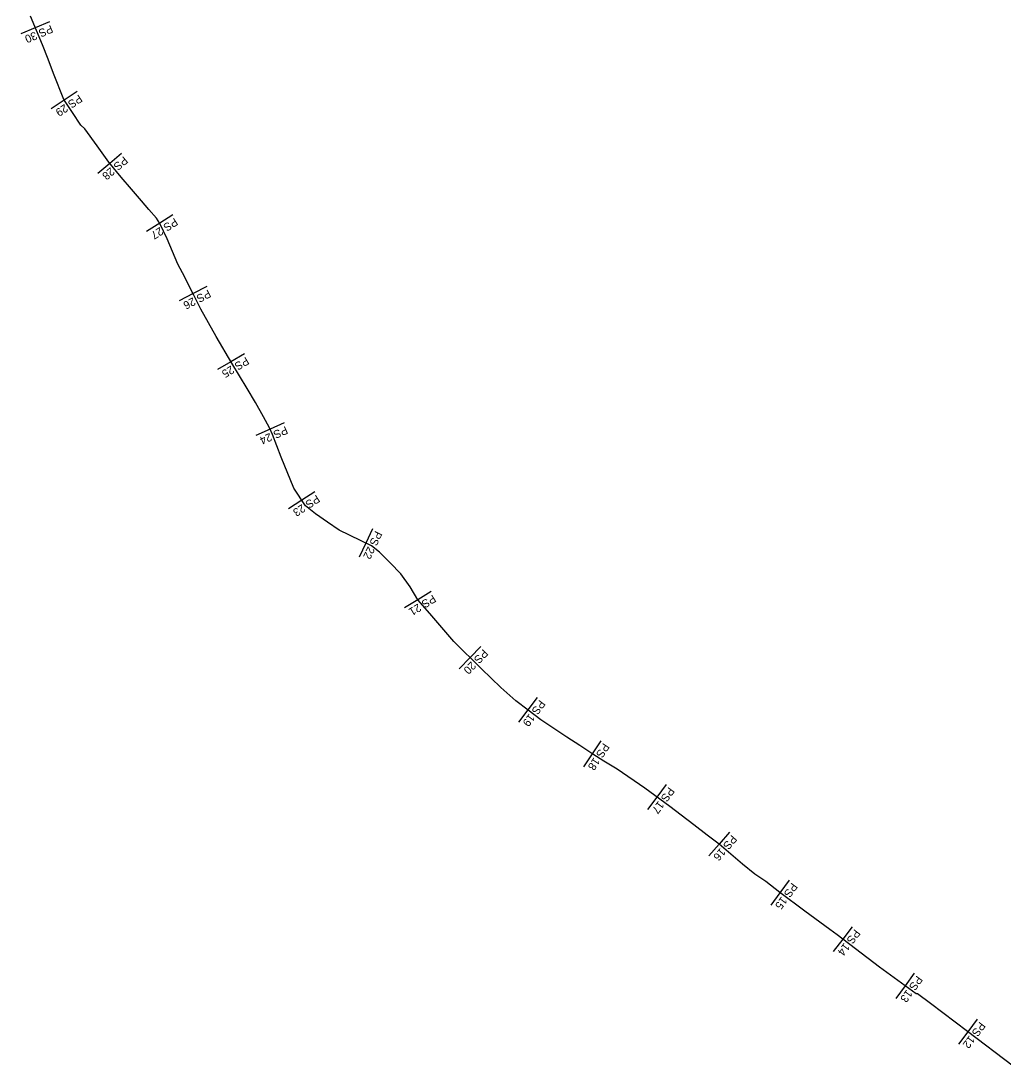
# Model space of a CAD drawing. Extents: x -844670 to -843025, y -997533 to -995513.
# Drawn here: x -844321 to -843691, y -997184 to -996514 of the extents above; entities that cross this region are included whole.
import ezdxf

# ---------------------------------------------------------------- set-up
doc = ezdxf.new("R2010")
doc.units = 0
doc.layers.add('Osa', color=7, linetype='Continuous')
doc.layers.add('Řezy', color=7, linetype='Continuous')

msp = doc.modelspace()

# ---------------------------------------------------------------- linework, layer by layer
at = {"layer": 'Osa'}
msp.add_lwpolyline([(-843685.02, -997184.17), (-843714.34, -997161.92), (-843737.99, -997144.05), (-843746.29, -997137.86), (-843747.28, -997137.77), (-843770.7, -997120.79), (-843797.77, -997100.1), (-843802.48, -997096.6), (-843818.53, -997084.86), (-843834.64, -997072.98), (-843843.67, -997065.86), (-843850.66, -997061.13), (-843858.57, -997054.8), (-843873.56, -997041.84), (-843881.27, -997036.04), (-843889.86, -997029.57), (-843897.98, -997023.38), (-843905.21, -997017.86), (-843921.14, -997005.98), (-843938.96, -996993.88), (-843947.49, -996988.62), (-843954.56, -996984.21), (-843962.93, -996978.74), (-843971.3, -996973.27), (-843979.6, -996967.7), (-843987.91, -996962.14), (-843995.94, -996956.08), (-844003.97, -996950.02), (-844013.59, -996941.43), (-844025.89, -996929.51), (-844043.74, -996912.06), (-844059.14, -996894.1), (-844066.71, -996885.26), (-844071.81, -996876.85), (-844077.67, -996868.54), (-844084.49, -996861.61), (-844091.32, -996854.69), (-844096.43, -996850.63), (-844117.33, -996840.69), (-844124.83, -996835.47), (-844132.33, -996830.24), (-844138.88, -996825.09), (-844146.3, -996813.66), (-844154.54, -996793.89), (-844157.3, -996786.63), (-844160.06, -996779.38), (-844161.95, -996775.05), (-844165.76, -996767.93), (-844170.99, -996758.84), (-844176.21, -996749.76), (-844186.05, -996733.62), (-844196.21, -996716.4), (-844205.92, -996698.84), (-844210.47, -996689.97), (-844217.82, -996675.58), (-844220.61, -996670.05), (-844224.05, -996661.97), (-844227.49, -996653.89), (-844232.17, -996644.05), (-844234.41, -996640.51), (-844239.23, -996635.04), (-844244.06, -996629.58), (-844250.52, -996621.94), (-844256.98, -996614.3), (-844264.96, -996604.81), (-844272.51, -996594.14), (-844280.44, -996583.43), (-844282.85, -996581.06), (-844288.34, -996572.81), (-844293.83, -996564.57), (-844300.43, -996547.97), (-844303.97, -996538.71), (-844307.53, -996529.45), (-844315.28, -996511.19)], dxfattribs=at)
at = {"layer": 'Řezy'}
for points in [[(-844302.95, -996514.65), (-844312.15, -996518.56), (-844321.36, -996522.47)], [(-844285.25, -996559.42), (-844293.57, -996564.96), (-844301.89, -996570.5)], [(-844256.73, -996599.05), (-844264.39, -996605.48), (-844272.05, -996611.91)], [(-844223.88, -996638.45), (-844232.33, -996643.8), (-844240.78, -996649.14)], [(-844202.07, -996684.43), (-844210.98, -996688.98), (-844219.88, -996693.53)], [(-844178.01, -996727.56), (-844186.63, -996732.64), (-844195.24, -996737.72)], [(-844152.41, -996771.89), (-844161.58, -996775.89), (-844170.74, -996779.9)], [(-844132.87, -996815.98), (-844141.26, -996821.42), (-844149.65, -996826.86)], [(-844095.87, -996839.82), (-844100.16, -996848.85), (-844104.45, -996857.89)], [(-844058.22, -996879.98), (-844066.77, -996885.17), (-844075.32, -996890.35)], [(-844026.31, -996915.11), (-844033.3, -996922.26), (-844040.29, -996929.41)], [(-843990.28, -996947.82), (-843996.3, -996955.8), (-844002.32, -996963.79)], [(-843949.51, -996975.57), (-843954.99, -996983.94), (-843960.46, -996992.3)], [(-843907.47, -997003.7), (-843913.44, -997011.72), (-843919.42, -997019.74)], [(-843867.01, -997034.29), (-843873.55, -997041.85), (-843880.08, -997049.42)], [(-843828.6, -997065.01), (-843834.53, -997073.06), (-843840.47, -997081.11)], [(-843788.23, -997094.8), (-843794.3, -997102.75), (-843800.37, -997110.69)], [(-843748.4, -997124.6), (-843754.27, -997132.7), (-843760.14, -997140.79)], [(-843707.99, -997154.18), (-843714.04, -997162.15), (-843720.08, -997170.11)]]:
    msp.add_lwpolyline(points, dxfattribs=at)

# ---------------------------------------------------------------- texts
for s, rotation, p in [('PS 30', 203.01087, (-844302.14, -996516.54)), ('PS 29', 213.666, (-844284.11, -996561.12)), ('PS 28', 220.00973, (-844255.41, -996600.62)), ('PS 27', 212.32433, (-844222.78, -996640.18)), ('PS 26', 207.03666, (-844201.14, -996686.26)), ('PS 25', 210.52654, (-844176.97, -996729.33)), ('PS 24', 203.60505, (-844151.59, -996773.77)), ('PS 23', 212.94987, (-844131.75, -996817.71)), ('PS 22', 244.57496, (-844094.01, -996840.7)), ('PS 21', 211.21387, (-844057.15, -996881.74)), ('PS 20', 225.66526, (-844024.85, -996916.54)), ('PS 19', 232.96503, (-843988.64, -996949.06)), ('PS 18', 236.80258, (-843947.79, -996976.69)), ('PS 17', 233.2858, (-843905.82, -997004.93)), ('PS 16', 229.16502, (-843865.45, -997035.63)), ('PS 15', 233.5823, (-843826.94, -997066.23)), ('PS 14', 232.60879, (-843786.6, -997096.05)), ('PS 13', 234.05929, (-843746.74, -997125.81)), ('PS 12', 232.80482, (-843706.36, -997155.42))]:
    msp.add_text(s, height=5.132, rotation=rotation, dxfattribs=at).set_placement(p)

doc.saveas('drawing.dxf')
